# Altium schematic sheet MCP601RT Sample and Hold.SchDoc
size A3; Author: Burmeister; DrawnBy: Burmeister; Engineer: Burmeister; Organization: RUETZ TECHNOLOGIES; Address1: Walter-Gropius-Str. 17; Address2: 80807; Address3: München; Address4: Germany; DocumentNumber: 11; Revision: 1.0; SheetNumber: 11; SheetTotal: 17; Abteilung: Hard/Software Entwicklung; Datum_V1: 30.7.2012; Version_V1: 1.0; Ersteller_V1: Burmeister
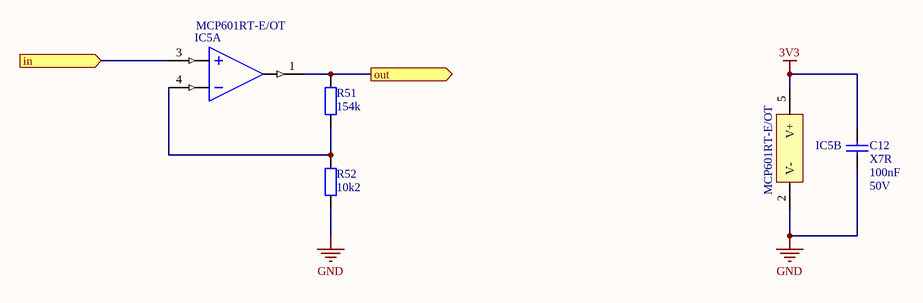
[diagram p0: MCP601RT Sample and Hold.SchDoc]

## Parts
C12  A_Charakteristik: X7R  L_Spannung: 50V  [RLCDT_0603]  (hidden comment: 100nF)
IC5  MCP601RT-E/OT  [IC_SOT23-5]  (parts A,B of 2)
R51  154k  [RLCDT_0603]
R52  10k2  [RLCDT_0603]

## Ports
in (in), out (out)

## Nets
3V3: C12.2 IC5.5(V+)
GND: C12.1 IC5.2(V-) R52.2
in: IC5.3(IN+) ; port in
out: IC5.1(OUT) R51.1 ; port out
NetIC5_4: IC5.4(IN-) R51.2 R52.1

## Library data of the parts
C12 = C_KERAMIK: Kondensator, Keramik; W_Erstellt: MRipel; H_Temp_min: -55°C; I_Temp_max: 125°C; D_Hersteller: KEMET; E_Herstellerbezeichnung: C0603C104K5RAC; B_Bestellnummer: 1288255; J_Richtpreis_10: 0.025; K_Richtpreis_100: 0.024; G_Wird_beigestellt: Nein; A_Update_From_DB: Ja; A_Database_ID: RLCDT_C_Ker_01; F_LAGERNUMMER: keine
IC5 = IC_OPA_MCP601: Ultra-Small, Low-Cost,  Op Amps with  Rail-to-Rail Outputs; H_Temp_min: -40°C; I_Temp_max: 125°C; D_Hersteller: MICROCHIP; B_Bestellnummer: 1840904; J_Richtpreis_10: 0.336; K_Richtpreis_100: 0.301; W_Erstellt: Burmeister; L_Spannung: 2.7V  - 6V; G_Wird_beigestellt: Nein; A_Update_from_DB: Ja; A_Database_ID: IC_223; F_LAGERNUMMER: Aus Datenbank
R51 = R: Widerstand; W_Erstellt: MRipel; J_Richtpreis_10: 0.01; G_Wird_beigestellt: Nein; A_Update_From_DB: Ja; A_Database_ID: RLCDT_R_E96_1075; A_Charakteristik: 1%
R52 = R: Widerstand; W_Erstellt: MRipel; J_Richtpreis_10: 0.01; G_Wird_beigestellt: Nein; A_Update_From_DB: Ja; A_Database_ID: RLCDT_R_E96_962; A_Charakteristik: 1%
